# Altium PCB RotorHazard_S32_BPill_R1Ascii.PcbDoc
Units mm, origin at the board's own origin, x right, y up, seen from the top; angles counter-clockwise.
Board outline 100 x 100 mm, 2 copper layers (Top Layer, Bottom Layer), stack 1.671 mm thick; 43 components, 65 nets, 291 pads, 44 vias.
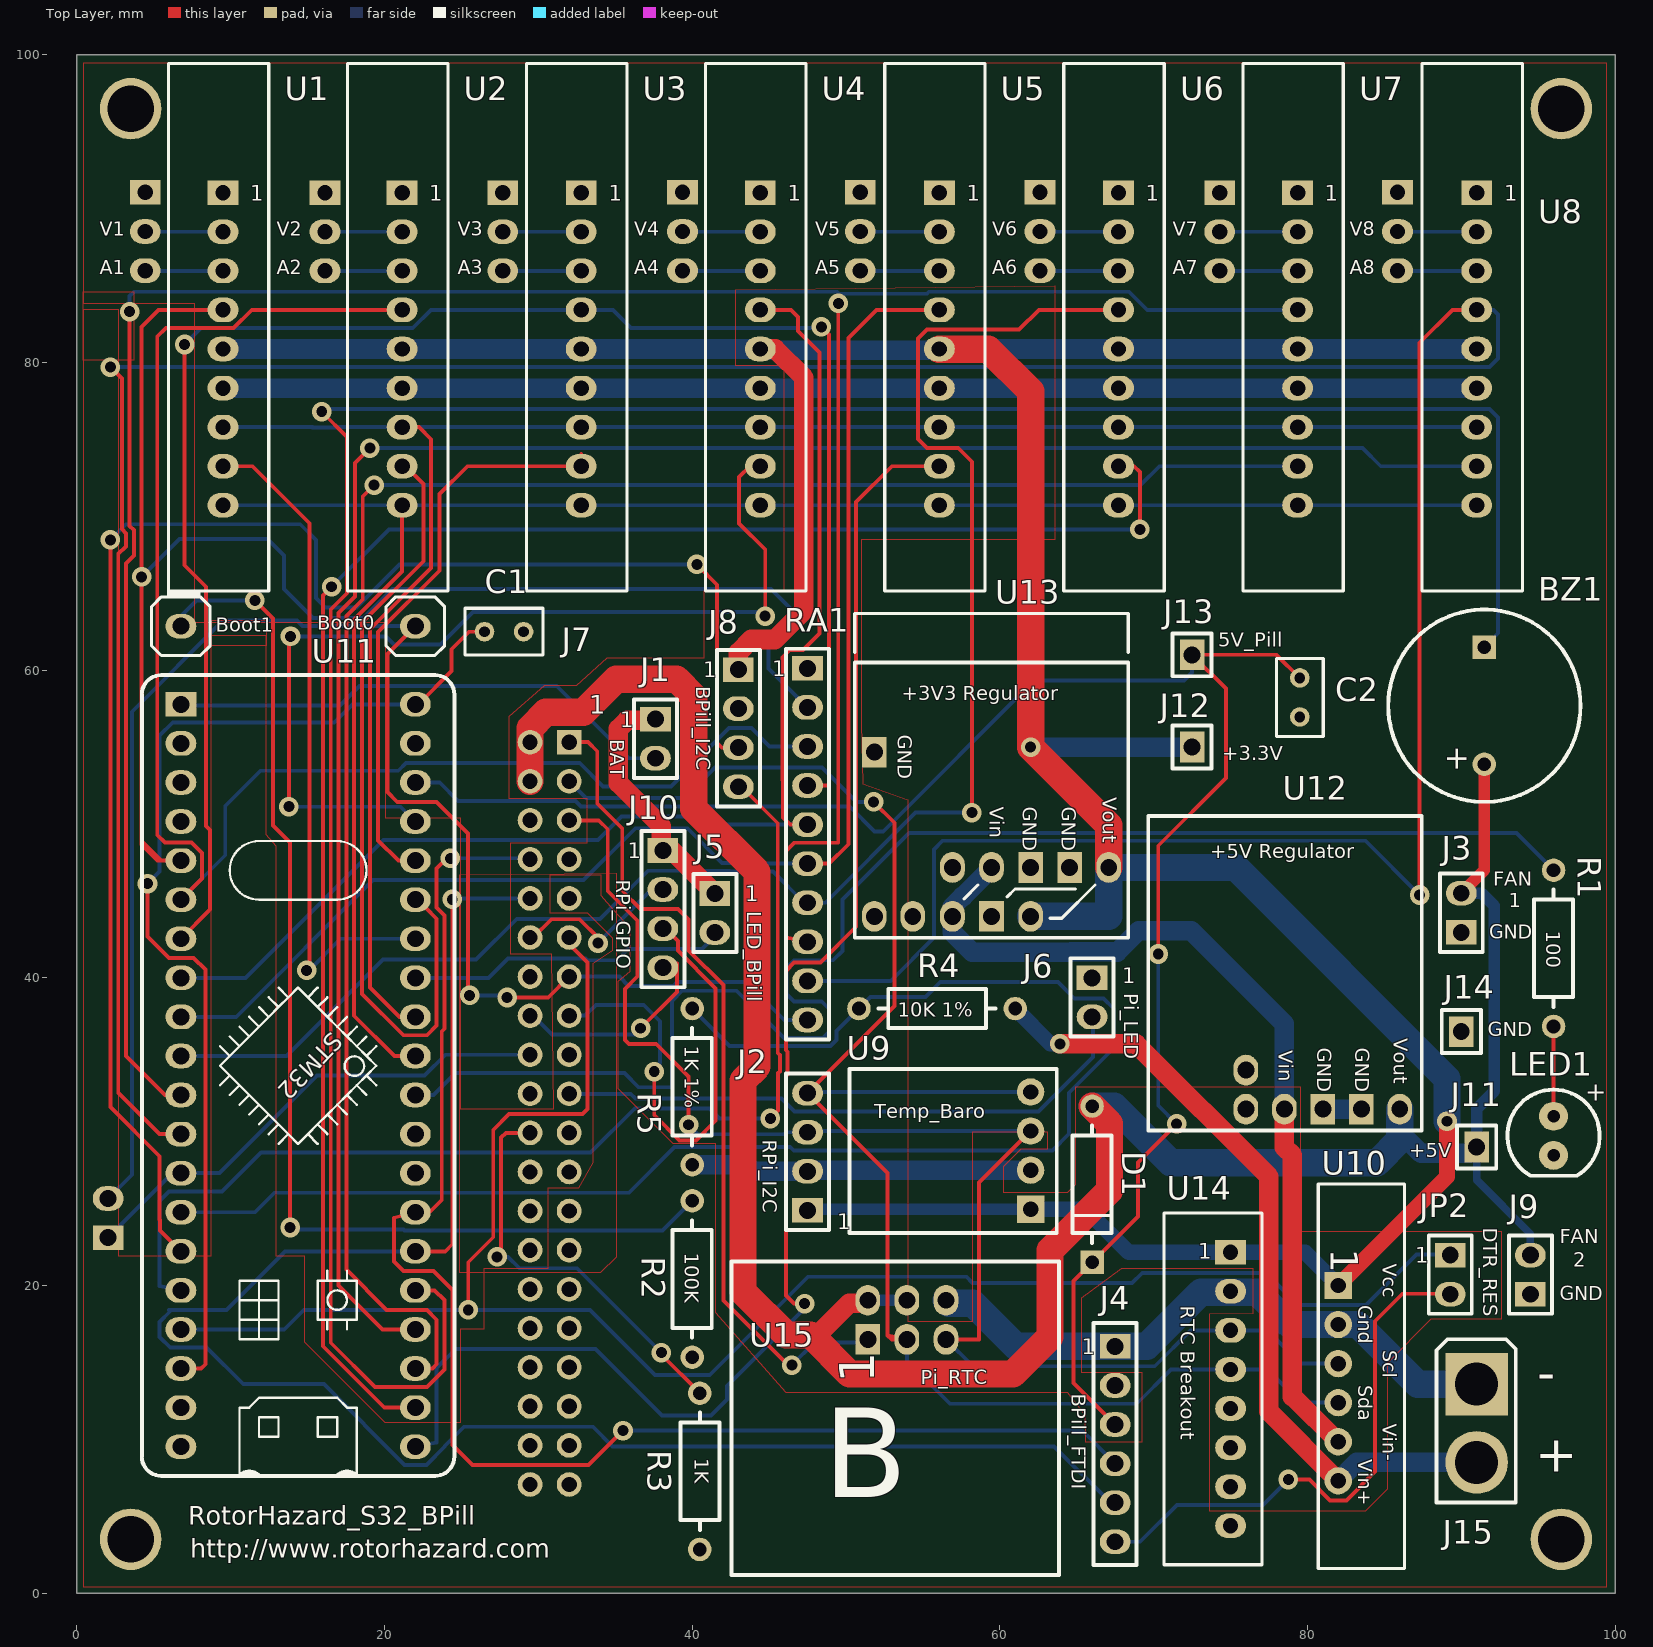
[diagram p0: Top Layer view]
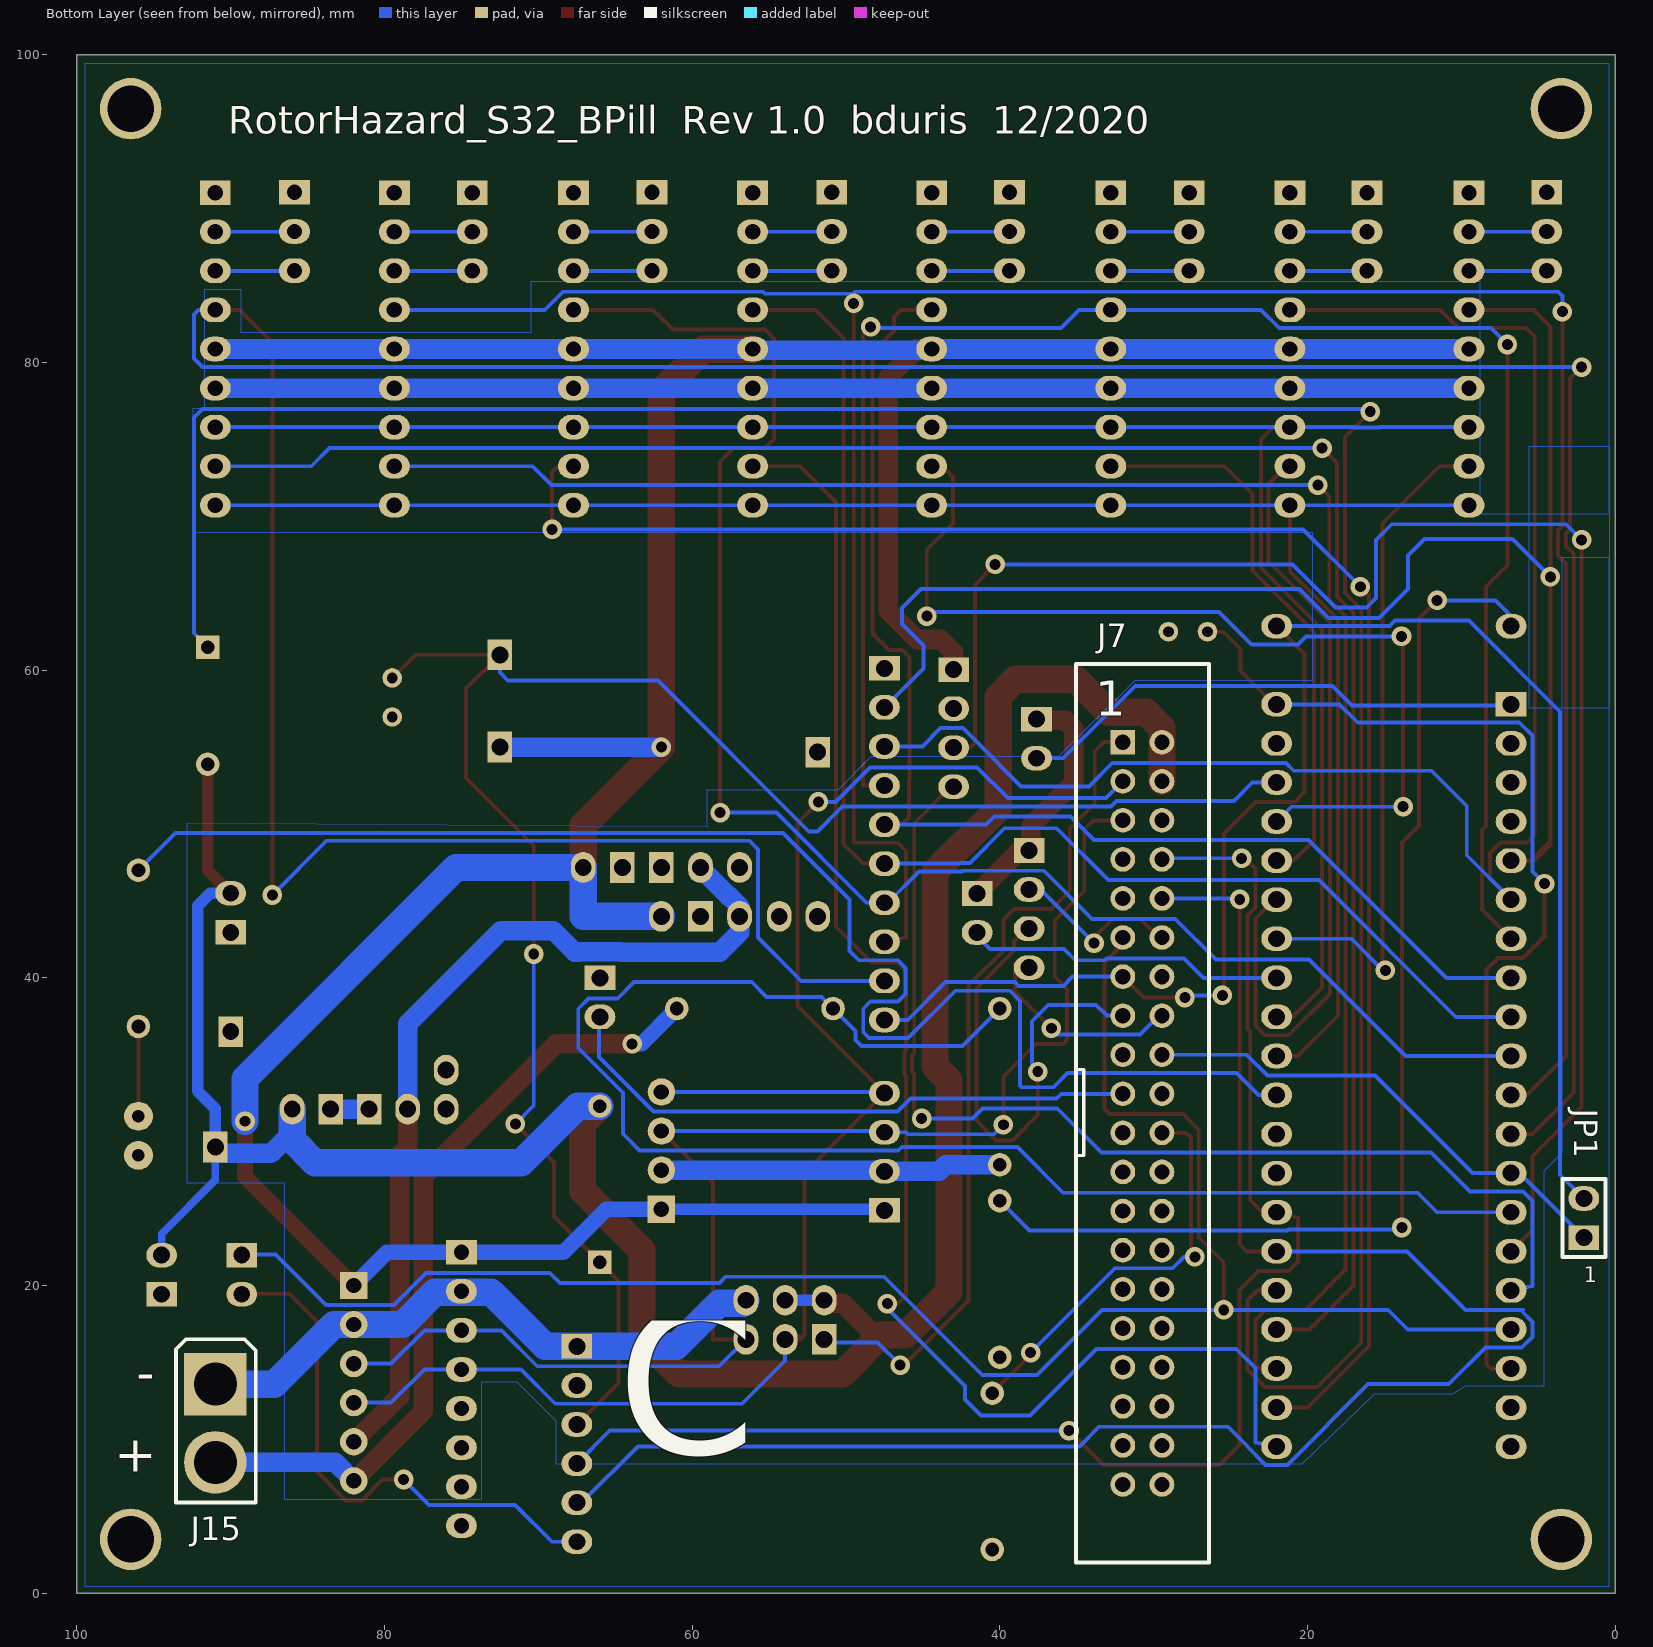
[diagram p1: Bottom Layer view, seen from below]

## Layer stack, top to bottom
Top Solder: solder mask 0.0102, Solder Resist, Dk 3.5
Top Layer: signal copper 0.0356
Dielectric 1: dielectric 1.6, FR-4, Dk 4.8
Bottom Layer: signal copper 0.0356
Bottom Solder: solder mask 0.0102, Solder Resist, Dk 3.5

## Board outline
0,0 100,0 100,100 0,100

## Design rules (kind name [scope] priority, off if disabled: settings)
AssemblyTestPointUsage [All] p0: scope1count=1 scope1_0_kind=Board scope1_0_value=Board scope2count=1 scope2_0_kind=Board scope2_0_value=Board commentlength=0
AssemblyTestpoint [All] p0: scope1count=1 scope1_0_kind=Board scope1_0_value=Board scope2count=1 scope2_0_kind=Board scope2_0_value=Board commentlength=0
Clearance [All] p0: scope1count=1 scope1_0_kind=Board scope1_0_value=Board scope2count=1 scope2_0_kind=Board scope2_0_value=Board commentlength=0 gap=0.254
Clearance [All] p1: gap=0.254
ComponentClearance [All] p0: scope1count=1 scope1_0_kind=Board scope1_0_value=Board scope2count=1 scope2_0_kind=Board scope2_0_value=Board commentlength=0 gap=0.254 collisioncheckmode=3
DiffPairsRouting [All] p0: scope1count=1 scope1_0_kind=Board scope1_0_value=Board scope2count=1 scope2_0_kind=Board scope2_0_value=Board commentlength=0
FabricationTestPointUsage [All] p0: scope1count=1 scope1_0_kind=Board scope1_0_value=Board scope2count=1 scope2_0_kind=Board scope2_0_value=Board commentlength=0 valid=0 allowmultiple=FALSE
FabricationTestpoint [All] p0: scope1count=1 scope1_0_kind=Board scope1_0_value=Board scope2count=1 scope2_0_kind=Board scope2_0_value=Board commentlength=0 side=3 testpointundercomponent=TRUE minsize=1.016 maxsize=2.54 preferedsize=1.524 minholesize=0 maxholesize=1.016 preferedholesize=0.813 testpointgrid=0.025
FanoutControl Fanout_Default [All] p0: scope1count=1 scope1_0_kind=Board scope1_0_value=Board scope2count=1 scope2_0_kind=Board scope2_0_value=Board commentlength=30 // Fanout_Default (Default Rule)
FanoutControl Fanout_Small [All] p0 off: scope1count=1 scope1_0_kind=Board scope1_0_value=Board scope2count=1 scope2_0_kind=Board scope2_0_value=Board commentlength=84 // Protel DXP Scope 1 Expression Was: (CompPinCount < 5)   Fanout_Small (Default Rule)
FanoutControl Fanout_SOIC [All] p0 off: scope1count=1 scope1_0_kind=Board scope1_0_value=Board scope2count=1 scope2_0_kind=Board scope2_0_value=Board commentlength=71 // Protel DXP Scope 1 Expression Was: IsSOIC   Fanout_SOIC (Default Rule)
FanoutControl Fanout_LCC [All] p0 off: scope1count=1 scope1_0_kind=Board scope1_0_value=Board scope2count=1 scope2_0_kind=Board scope2_0_value=Board commentlength=69 // Protel DXP Scope 1 Expression Was: IsLCC   Fanout_LCC (Default Rule)
FanoutControl Fanout_BGA [All] p0 off: scope1count=1 scope1_0_kind=Board scope1_0_value=Board scope2count=1 scope2_0_kind=Board scope2_0_value=Board commentlength=69 // Protel DXP Scope 1 Expression Was: IsBGA   Fanout_BGA (Default Rule)
Height [All] p0: scope1count=1 scope1_0_kind=Board scope1_0_value=Board scope2count=1 scope2_0_kind=Board scope2_0_value=Board commentlength=0
Height [All] p1: minheight=0 maxheight=38.1 prefheight=12.7
HoleSize [All] p0: scope1count=1 scope1_0_kind=Board scope1_0_value=Board scope2count=1 scope2_0_kind=Board scope2_0_value=Board commentlength=0 absolutevalues=TRUE maxlimit=6.35 minlimit=0.025 maxpercent=80.000 minpercent=20.000
HoleSize [All] p1: absolutevalues=TRUE maxlimit=6.35 minlimit=0.025 maxpercent=80.000 minpercent=20.000
HoleToHoleClearance [All] p0: scope1count=1 scope1_0_kind=Board scope1_0_value=Board scope2count=1 scope2_0_kind=Board scope2_0_value=Board commentlength=0
LayerPairs [All] p0: scope1count=1 scope1_0_kind=Board scope1_0_value=Board scope2count=1 scope2_0_kind=Board scope2_0_value=Board commentlength=0 enforce=TRUE
MinimumSolderMaskSliver [All] p0: scope1count=1 scope1_0_kind=Board scope1_0_value=Board scope2count=1 scope2_0_kind=Board scope2_0_value=Board commentlength=0
NetAntennae [All] p0: scope1count=1 scope1_0_kind=Board scope1_0_value=Board scope2count=1 scope2_0_kind=Board scope2_0_value=Board commentlength=0
PasteMaskExpansion [All] p0: scope1count=1 scope1_0_kind=Board scope1_0_value=Board scope2count=1 scope2_0_kind=Board scope2_0_value=Board commentlength=0 expansion=0
PlaneClearance [All] p0: scope1count=1 scope1_0_kind=Board scope1_0_value=Board scope2count=1 scope2_0_kind=Board scope2_0_value=Board commentlength=0 clearance=0.508
PlaneConnect [All] p0: scope1count=1 scope1_0_kind=Board scope1_0_value=Board scope2count=1 scope2_0_kind=Board scope2_0_value=Board commentlength=0 planeconnectstyle=Relief reliefexpansion=0.508 reliefentries=4 reliefconductorwidth=0.381 reliefairgap=0.254
PlaneConnect [All] p1: planeconnectstyle=Relief reliefexpansion=0.508 reliefentries=4 reliefconductorwidth=0.381 reliefairgap=0.254
PolygonConnect [All] p0: scope1count=1 scope1_0_kind=Board scope1_0_value=Board scope2count=1 scope2_0_kind=Board scope2_0_value=Board commentlength=0 connectstyle=Relief reliefconductorwidth=0.381 reliefentries=4 polygonreliefangle="90 Angle"
PolygonConnect [All] p1: connectstyle=Relief reliefconductorwidth=0.381 reliefentries=4 polygonreliefangle="90 Angle" airgapwidth=0.254
RoutingCorners [All] p0: scope1count=1 scope1_0_kind=Board scope1_0_value=Board scope2count=1 scope2_0_kind=Board scope2_0_value=Board commentlength=0 cornerstyle=45-Degree minsetback=2.54 maxsetback=2.54
RoutingLayers [All] p0: scope1count=1 scope1_0_kind=Board scope1_0_value=Board scope2count=1 scope2_0_kind=Board scope2_0_value=Board commentlength=0 top layer=Automatic bottom layer=Automatic
RoutingPriority [All] p0: scope1count=1 scope1_0_kind=Board scope1_0_value=Board scope2count=1 scope2_0_kind=Board scope2_0_value=Board commentlength=0
RoutingTopology [All] p0: scope1count=1 scope1_0_kind=Board scope1_0_value=Board scope2count=1 scope2_0_kind=Board scope2_0_value=Board commentlength=0 topology=Shortest
RoutingVias [All] p0: scope1count=1 scope1_0_kind=Board scope1_0_value=Board scope2count=1 scope2_0_kind=Board scope2_0_value=Board commentlength=0 holewidth=0.711 width=1.27 viastyle="Through Hole" minholewidth=0.711 minwidth=1.27 maxholewidth=0.711 maxwidth=1.27
RoutingVias [All] p1: holewidth=0.711 width=1.27 viastyle="Through Hole" minholewidth=0.711 minwidth=1.27 maxholewidth=0.711 maxwidth=1.27
ShortCircuit [All] p0: scope1count=1 scope1_0_kind=Board scope1_0_value=Board scope2count=1 scope2_0_kind=Board scope2_0_value=Board commentlength=0 allowed=FALSE
SilkToBoardRegionClearance [All] p0: scope1count=1 scope1_0_kind=Board scope1_0_value=Board scope2count=1 scope2_0_kind=Board scope2_0_value=Board commentlength=0
SilkToSilkClearance [All] p0: scope1count=1 scope1_0_kind=Board scope1_0_value=Board scope2count=1 scope2_0_kind=Board scope2_0_value=Board commentlength=0
SilkToSilkClearance [All] p1: silktosilkclearance=0.152
SilkToSolderMaskClearance [All] p0 off: scope1count=1 scope1_0_kind=Board scope1_0_value=Board scope2count=1 scope2_0_kind=Board scope2_0_value=Board commentlength=44 // Protel DXP Scope 1 Expression Was: IsPad
SilkToSolderMaskClearance [IsPad] p1: minsilkscreentomaskgap=0.152 clearancetoexposedcopper=TRUE
SolderMaskExpansion [All] p0: scope1count=1 scope1_0_kind=Board scope1_0_value=Board scope2count=1 scope2_0_kind=Board scope2_0_value=Board commentlength=0 expansion=0.102
SolderMaskExpansion [All] p1: expansion=0.102
UnRoutedNet [All] p0: scope1count=1 scope1_0_kind=Board scope1_0_value=Board scope2count=1 scope2_0_kind=Board scope2_0_value=Board commentlength=0
UnpouredPolygon [All] p0: scope1count=1 scope1_0_kind=Board scope1_0_value=Board scope2count=1 scope2_0_kind=Board scope2_0_value=Board commentlength=0
Width Width_5 [All] p0: scope1count=1 scope1_0_kind=Net scope1_0_value=+5V scope2count=1 scope2_0_kind=Board scope2_0_value=Board commentlength=0 maxlimit=2.54 minlimit=0.508 preferedwidth=0.762
Width Width_1 [All] p0: scope1count=1 scope1_0_kind=Board scope1_0_value=Board scope2count=1 scope2_0_kind=Board scope2_0_value=Board commentlength=0 maxlimit=0.254 minlimit=0.254 preferedwidth=0.254
Width Width_3V3 [All] p0: scope1count=1 scope1_0_kind=Net scope1_0_value=+3V3 scope2count=1 scope2_0_kind=Board scope2_0_value=Board commentlength=0 maxlimit=2.54 minlimit=0.762 preferedwidth=1.016
Width Width_GND [All] p0: scope1count=1 scope1_0_kind=Net scope1_0_value=GND scope2count=1 scope2_0_kind=Board scope2_0_value=Board commentlength=0 maxlimit=2.54 minlimit=0.762 preferedwidth=1.27
Width Width_VPWR_IN+ [All] p0: scope1count=1 scope1_0_kind=Net scope1_0_value=VPWR_IN+ scope2count=1 scope2_0_kind=Board scope2_0_value=Board commentlength=0 maxlimit=1.27 minlimit=0.762 preferedwidth=1.016
Width Width_VPWR_IN- [All] p0: scope1count=1 scope1_0_kind=Net scope1_0_value=VPWR_IN- scope2count=1 scope2_0_kind=Board scope2_0_value=Board commentlength=0 maxlimit=1.27 minlimit=0.762 preferedwidth=1.016
Width Width_GND [InNet('GND')] p1: maxlimit=2.54 minlimit=0.762 preferedwidth=1.27
Width Width_3V3 [InNet('+3V3')] p2: maxlimit=2.54 minlimit=0.762 preferedwidth=1.016
Width Width_5 [InNet('+5V')] p3: maxlimit=2.54 minlimit=0.508 preferedwidth=0.762
Width Width_VPWR_IN+ [InNet('VPWR_IN+')] p4: maxlimit=1.27 minlimit=0.762 preferedwidth=1.016
Width Width_VPWR_IN- [InNet('VPWR_IN-')] p5: maxlimit=1.27 minlimit=0.762 preferedwidth=1.016
Width Width_1 [All] p6: maxlimit=0.254 minlimit=0.254 preferedwidth=0.254
25 further rules are at their usual default settings.

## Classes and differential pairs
net class RSSI_[1..8]: RSSI_1 RSSI_2 RSSI_3 RSSI_4 RSSI_5 RSSI_6 RSSI_7 RSSI_8
net class RX_SEL_[1..8]: RX_SEL_1 RX_SEL_2 RX_SEL_3 RX_SEL_4 RX_SEL_5 RX_SEL_6 RX_SEL_7 RX_SEL_8

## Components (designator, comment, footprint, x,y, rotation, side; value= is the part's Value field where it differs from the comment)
BZ1 "TMB12A05" BZ_12mm 91.5,61.5 r90 top
C1 "0.1uF 50V X7R" "Cap Radial 100mil" 29.04,62.5 r180 top
C2 "0.1uF 50V X7R" "Cap Radial 100mil" 79.5,56.96 r90 top
D1 "MBR100RLG" "Axial 0.4 Diode" 66,31.66 r270 top
J1 "HDR 1X2" "HDR 1x2_2.54mm" 37.611,56.813 r0 top
J2 "HDR 1X4" "HDR 1x4_2.54mm" 47.5,24.88 r180 top
J3 "HDR 1X2" "HDR 1x2_2.54mm" 90,42.96 r180 top
J4 "6 PIN SIL VERT SOCKET" "6-PIN SIL VERT SOCKET" 67.5,16.04 r0 top
J5 "HDR 1X2" "HDR 1x2_2.54mm" 41.472,45.485 r0 top
J6 "HDR 1X2" "HDR 1x2_2.54mm" 66,40 r0 top
J7 "Header_2X20_Vert_Thru" Header_2X20_Vert_Thru 30.73,31.19 r180 bottom
J8 "HDR 1X4" "HDR 1x4_2.54mm" 43,60.04 r0 top
J9 "HDR 1X2" "HDR 1x2_2.54mm" 94.488,19.431 r180 top
J10 "HDR 1X4" "HDR 1x4_2.54mm" 38.094,48.279 r0 top
J11 "HDR 1X1" "HDR 1x1_2.54mm" 91,29 r90 top
J12 "HDR 1X1" "HDR 1x1_2.54mm" 72.5,55 r90 top
J13 "HDR 1X1" "HDR 1x1_2.54mm" 72.5,61 r90 top
J14 "HDR 1X1" "HDR 1x1_2.54mm" 90,36.5 r90 top
J15 "XT30-M" XT30_M 91,13.58 r0 bottom
JP1 "HDR 1X2" "HDR 1x2_2.54mm" 2.032,23.114 r0 bottom
JP2 "HDR 1X2" "HDR 1x2_2.54mm" 89.281,21.971 r0 top
LED1 "LED_5mm" LED_5mm 96,31 r270 top
R1 "100 1/4W 5%" "Axial 0.4 100 CF" 96,36.84 r90 top
R2 "100K 1/4W 5%" "Axial 0.4 100K CF" 40,15.34 r90 top
R3 "1K 1/4W 5%" "Axial 0.4 1K CF" 40.5,2.84 r90 top
R4 "10K 1/4W 1%" "Axial 0.4 10K MF" 50.84,38 r0 top
R5 "1K 1/4W 1%" "Axial 0.4 1K MF" 40,27.84 r90 top
RA1 "100K 10Pin SIP" RES_SIP_10P 47.5,60.12 r0 top
U1 "RX5808_PCB" RH_S32_Node_PCB 9.5,91.04 r0 top
U2 "RX5808_PCB" RH_S32_Node_PCB 21.143,91.04 r0 top
U3 "RX5808_PCB" RH_S32_Node_PCB 32.786,91.04 r0 top
U4 "RX5808_PCB" RH_S32_Node_PCB 44.429,91.04 r0 top
U5 "RX5808_PCB" RH_S32_Node_PCB 56.071,91.04 r0 top
U6 "RX5808_PCB" RH_S32_Node_PCB 67.714,91.04 r0 top
U7 "RX5808_PCB" RH_S32_Node_PCB 79.357,91.04 r0 top
U8 "RX5808_PCB" RH_S32_Node_PCB 91,91.04 r0 top
U9 "BME280_BRD" BME280_PCB 62,24.96 r90 top
U10 "INA219_BRD" INA219_PCB_RA 82,20 r270 top
U11 "STM32F103XX BPill" DIP40_Plus2 14.38,36.19 r0 top
U12 "D36V28F5" D36V28FX 76,31.46 r0 top
U13 "D24V22F3" D24V22FX 51.84,44 r0 top
U14 "DS3231_BBRD" DS3231_Breakout 75,22.16 r0 top
U15 "DS3231_Pi_RTC" Pi_RTC 75.55,17.77 r90 top

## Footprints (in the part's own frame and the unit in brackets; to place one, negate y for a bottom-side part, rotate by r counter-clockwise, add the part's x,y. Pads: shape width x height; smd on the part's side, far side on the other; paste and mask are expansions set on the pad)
"6-PIN SIL VERT SOCKET" [mm]
  rect 2x1.6 hole 1.1: 1(0,0)
  oval 2x1.6 hole 1.1: 2(0,-2.54) 3(0,-5.08) 4(0,-7.62) 5(0,-10.16) 6(0,-12.7)
  silkscreen extent -1.4,-14.22 1.4,1.52
"Axial 0.4 1K CF" [mil]
  round 60 hole 35: 1(0,0) 2(400,0)
  silkscreen extent 50,-50 350,50
"Axial 0.4 1K MF" [mil]
  round 60 hole 35: 1(0,0) 2(400,0)
  silkscreen extent 50,-50 350,50
"Axial 0.4 10K MF" [mil]
  round 60 hole 35: 1(0,0) 2(400,0)
  silkscreen extent 50,-50 350,50
"Axial 0.4 100 CF" [mil]
  round 60 hole 35: 1(0,0) 2(400,0)
  silkscreen extent 50,-50 350,50
"Axial 0.4 100K CF" [mil]
  round 60 hole 35: 1(0,0) 2(400,0)
  silkscreen extent 50,-50 350,50
"Axial 0.4 Diode" [mil]
  round 60 hole 35: A(0,0)
  rect 60x60 hole 35: K(400,0)
  silkscreen extent 50,-50 350,50
BME280_PCB [mil] "BME280 Temp Humidity and Pressure Breakout Board"
  rect 70x70 hole 39.37: 1(0,0)
  round 70 hole 39.37: 2(100,0) 3(200,0) 4(300,0)
  silkscreen extent -61,-67 359,463
BZ_12mm [mil]
  rect 60x60 hole 35: 1(0,0)
  round 60 hole 35: 2(-300,0)
  silkscreen extent -396,-246 96,246
"Cap Radial 100mil" [mil]
  round 50 hole 28: 1(0,0) 2(100,0)
  silkscreen extent -50,-60 150,60
D24V22FX [mm] "Pololu D24V22FX Series pad layout and body"
  oval 1.6x2 hole 1.1: 1(0,0) 2(2.5,0) 3(5.08,0) 5(10.16,0)
  rect 1.6x2 hole 1.1: 4(7.62,0) 6(0,10.668)
  silkscreen extent -1.27,-1.4 16.51,16.51
D36V28FX [mm] "Pololu D36V28FX Series DC/DC Converter"
  oval 1.6x2 hole 1.1: 1(0,0) 2(2.5,0) 5(10,0) 6(0,2.54)
  rect 1.6x2 hole 1.1: 3(5,0) 4(7.5,0)
  silkscreen extent -6.35,-1.4 11.43,19.05
DIP40_Plus2 [mm]
  rect 2x1.6 hole 1.1: 1(-7.62,21.59)
  oval 2x1.6 hole 1.1: 2(-7.62,19.05) 3(-7.62,16.51) 4(-7.62,13.97) 5(-7.62,11.43) 6(-7.62,8.89) 7(-7.62,6.35) 8(-7.62,3.81) 9(-7.62,1.27) 10(-7.62,-1.27) 11(-7.62,-3.81) 12(-7.62,-6.35) 13(-7.62,-8.89) 14(-7.62,-11.43) 15(-7.62,-13.97) 16(-7.62,-16.51) 17(-7.62,-19.05) 18(-7.62,-21.59) 19(-7.62,-24.13) 20(-7.62,-26.67) 21(7.62,-26.67) 22(7.62,-24.13) 23(7.62,-21.59) 24(7.62,-19.05) 25(7.62,-16.51) 26(7.62,-13.97) 27(7.62,-11.43) 28(7.62,-8.89) 29(7.62,-6.35) 30(7.62,-3.81) 31(7.62,-1.27) 32(7.62,1.27) 33(7.62,3.81) 34(7.62,6.35) 35(7.62,8.89) 36(7.62,11.43) 37(7.62,13.97) 38(7.62,16.51) 39(7.62,19.05) 40(7.62,21.59) 41(7.62,26.67) 42(-7.62,26.67)
  silkscreen extent -10.16,-28.57 10.16,28.57
DS3231_Breakout [mm] "Adafruit DS3231 RTC Breakout Board"
  rect 2x1.6 hole 1: 1(0,0)
  oval 2x1.6 hole 1: 2(0,-2.54) 3(0,-5.08) 4(0,-7.62) 5(0,-10.16) 6(0,-12.7) 7(0,-15.24) 8(0,-17.78)
  silkscreen extent -4.32,-20.32 2.03,2.54
"HDR 1x1_2.54mm" [mm]
  rect 2x1.6 hole 1.1: 1(0,0)
  silkscreen extent -1.4,-1.27 1.4,1.27
"HDR 1x2_2.54mm" [mm]
  rect 2x1.6 hole 1.1: 1(0,0)
  oval 2x1.6 hole 1.1: 2(0,-2.54)
  silkscreen extent -1.4,-3.81 1.4,1.27
"HDR 1x4_2.54mm" [mm]
  rect 2x1.6 hole 1.1: 1(0,0)
  oval 2x1.6 hole 1.1: 2(0,-2.54) 3(0,-5.08) 4(0,-7.62)
  silkscreen extent -1.4,-8.89 1.4,1.27
Header_2X20_Vert_Thru [mm]
  rect 1.6x1.6 hole 1: 1(-1.27,24.13)
  round 1.6 hole 1: 2(1.27,24.13) 3(-1.27,21.59) 4(1.27,21.59) 5(-1.27,19.05) 6(1.27,19.05) 7(-1.27,16.51) 8(1.27,16.51) 9(-1.27,13.97) 10(1.27,13.97) 11(-1.27,11.43) 12(1.27,11.43) 13(-1.27,8.89) 14(1.27,8.89) 15(-1.27,6.35) 16(1.27,6.35) 17(-1.27,3.81) 18(1.27,3.81) 19(-1.27,1.27) 20(1.27,1.27) 21(-1.27,-1.27) 22(1.27,-1.27) 23(-1.27,-3.81) 24(1.27,-3.81) 25(-1.27,-6.35) 26(1.27,-6.35) 27(-1.27,-8.89) 28(1.27,-8.89) 29(-1.27,-11.43) 30(1.27,-11.43) 31(-1.27,-13.97) 32(1.27,-13.97) 33(-1.27,-16.51) 34(1.27,-16.51) 35(-1.27,-19.05) 36(1.27,-19.05) 37(-1.27,-21.59) 38(1.27,-21.59) 39(-1.27,-24.13) 40(1.27,-24.13)
  silkscreen extent -4.32,-29.21 4.32,29.21
INA219_PCB_RA [mil] "Current and Voltage Sensor PCB with right-angle pins"
  rect 70x70 hole 39.37: 1(0,0)
  round 70 hole 39.37: 2(100,0) 3(200,0) 4(300,0) 5(400,0) 6(500,0)
  silkscreen extent -260,-51 724,169
LED_5mm [mil]
  round 74 hole 32: A(0,0) K(100,0)
  silkscreen extent -68,-118 152,118
Pi_RTC [mm] "Pins 1-6 of Pi header broken out for RTC"
  rect 2x1.6 hole 1.1: 1(-1.27,24.13)
  oval 2x1.6 hole 1.1: 2(1.27,24.13) 3(-1.27,21.59) 4(1.27,21.59) 5(-1.27,19.05) 6(1.27,19.05)
  silkscreen extent -16.6,11.7 3.8,33
RES_SIP_10P [mm] "Resistor Array 10-pin SIP"
  rect 2x1.6 hole 1.1: 1(0,0)
  oval 2x1.6 hole 1.1: 2(0,-2.54) 3(0,-5.08) 4(0,-7.62) 5(0,-10.16) 6(0,-12.7) 7(0,-15.24) 8(0,-17.78) 9(0,-20.32) 10(0,-22.86)
  silkscreen extent -1.4,-24.13 1.4,1.27
RH_S32_Node_PCB [mm] "RX5808 Module on PCB with RA Pins"
  rect 2x1.6 hole 1: 1(0,0)
  oval 2x1.6 hole 1: 2(0,-2.54) 3(0,-5.08) 4(0,-7.62) 5(0,-10.16) 6(0,-12.7) 7(0,-15.24) 8(0,-17.78) 9(0,-20.32)
  silkscreen extent -3.56,-25.88 2.97,8.41
XT30_M [mil] "XT30 connector male pins"
  rect 160x160 hole 110: 1(0,0)
  round 160 hole 110: 2(0,200)
  silkscreen extent -103,-115 100,303

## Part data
BZ1: library part Buzzer_12mm, "TMB12A05 12mmX9.5mm Buzzer"
C1 C2: library part C320C104K5R5TA7301, "Multilayer Ceramic Capacitors MLCC - Leaded 50V 0.1uF 10% X7R"
D1: library part MBR1100RLG, "Schottky Diodes & Rectifiers 1A 100V"
J1 J3 J5 J6 J9 JP1 JP2: library part 961102-6804-AR, "Headers & Wire Housings 2P STRT 1 ROW GOLD 6.8MM MATING PIN"
J2 J8 J10: library part 961104-6804-AR, "Headers & Wire Housings 4P STRT 1 ROW GOLD 6.8MM MATING PIN"
J4: library part M20-7820646, "Headers & Wire Housings 6 PIN SIL VERTICAL SOCKET TIN"
J7: library part Header_To_Pi_Cable
J11 J12 J13 J14: library part "HEADER 1X1", "Single pin header"
J15: "XT30 connector male pins"
LED1: "5mm standard leaded red LED"
R1: library part CFR-25JR-52-100R, "Carbon Film Resistors - Through Hole 100ohm 1/4W 5%"
R2: library part CFR-25JR-52-100K, "Carbon Film Resistors - Through Hole 100K ohm 1/4W 5%"
R3: library part CFR-25JT-52-1K, "Carbon Film Resistors - Through Hole 1/4W 1K Ohm 5%"
R4: library part MFR-25FRF52-10K, "Metal Film Resistors - Through Hole 10K ohm 1/4W 1%"
R5: library part MFR-25FRF52-1K, "Metal Film Resistors - Through Hole 1K ohm 1/4W 1%"
RA1: library part 4610X-101-104LF, "Resistor Networks & Arrays 10pins 100Kohms Bussed"
U1 U2 U3 U4 U5 U6 U7 U8: library part RH_S32_Node, "RX5808 module on PCB with right-angle header pins"
U9: library part BME280, "BME280 Temperature, Humidity and Pressure Sensor"
U10: "INA219 Current Sensor/Voltage Monitor"
U11: library part STM32F103XX_BPill, "STMF103XX BPill"
U12: "Pololu D36V28F5 DC/DC Converter"
U13: "Pololu D24V22F3 DC/DC Converter"
U14: library part DS3231_Breakout, "ADAFruit DS3231 Breakout Board"
U15: "ADAFruit DS3231 PiRTC"

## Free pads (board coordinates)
  round 4 hole 3: 0(96.5,96.5) 1(96.5,3.5) 2(3.5,3.5) 3(3.5,96.5)
  rect 2x1.6 hole 1: 1(4.445,91.059) 1(16.129,91.04) 1(27.686,91.04) 1(50.927,91.059) 1(62.611,91.059) 1(74.295,91.04) 1(85.852,91.059) 7(39.37,91.059)
  oval 1.6x2 hole 1.1: 1(56.92,47.175) 2(59.46,47.175) 5(67.08,47.175)
  oval 2x1.6 hole 1: 2(4.445,88.519) 2(16.129,88.5) 2(27.686,88.5) 2(39.37,88.519) 2(50.927,88.519) 2(62.611,88.519) 2(74.295,88.5) 2(85.852,88.519) 3(4.445,85.979) 3(16.129,85.96) 3(27.686,85.96) 3(39.37,85.979) 3(50.927,85.979) 3(62.611,85.979) 3(74.295,85.96) 3(85.852,85.979)
  rect 1.6x2 hole 1.1: 3(62,47.175) 4(64.54,47.175)

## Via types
v1: diameter 1.27, hole 0.711, Top Layer to Bottom Layer, 44 vias

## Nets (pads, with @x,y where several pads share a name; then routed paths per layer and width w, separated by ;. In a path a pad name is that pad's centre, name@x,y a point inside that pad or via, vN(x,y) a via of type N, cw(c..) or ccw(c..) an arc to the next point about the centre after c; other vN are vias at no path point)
3V3_PILL: C1.2 U11.18 U11.40 | length 70.1
  Top Layer w0.254: v1(4.591,46.12) 4.591,42.691 5.988,41.294 7.588,41.294 8.35,40.532 8.35,14.879 8.071,14.6 U11.18 ; U11.40 22.193,57.78 24.352,59.939 24.352,61.36 25.492,62.5 C1.2
  Bottom Layer w0.254: v1(4.591,46.12) 5.378,46.907 5.378,55.747 6.231,56.599 16.728,56.599 17.909,57.78 U11.40
5V_PILL: C2.2 D1.K J4.3 J13.1 U11.38 | length 122
  Top Layer w0.254: J4.3 64.789,13.671 64.789,20.289 D1.K 68.98,24.48 68.98,27.984 v1(71.495,30.499) ; v1(70.301,41.548) 70.301,48.584 74.695,52.978 74.695,58.805 J13.1 78,61 C2.2
  Bottom Layer w0.254: U11.38 23.589,52.7 24.784,51.505 32.405,51.505 32.769,51.141 50.243,51.141 51.86,49.524 52.419,49.524 62.224,59.328 71.992,59.328 72.5,59.836 J13.1 ; v1(70.301,41.548) 70.301,31.693 v1(71.495,30.499)
+3V3: J2.1 J8.1 J12.1 pad.5 U1.5 U2.5 U3.5 U4.5 U5.5 U6.5 U7.5 U8.5 U9.1 U10.1 U13.5 U14.1 | length 246.4
  Top Layer w1.016: J8.1 J8.1@43.021,60.04 ; U10.1 89.071,27.071 v1(89.071,30.677)
  Top Layer w1.27: J8.1 43,61.161 43.834,61.995 45.38,61.995 47.263,63.878 47.263,79.013 45.396,80.88 U4.5
  Top Layer w1.778: U5.5@56.071,80.867 59.257,80.867 62,78.124 62,55.005 v1(62.005,55) 67.08,49.925 pad.5
  Bottom Layer w0.762: J2.1 47.58,24.96 U9.1
  Bottom Layer w1.016: U9.1 65.57,24.96 68.37,22.16 U14.1 79.84,22.16 U10.1 ; U13.5 U13.5@62,44.012
  Bottom Layer w1.27: U1.5 U2.5 U3.5 U4.5 44.518,80.791 55.982,80.791 U5.5 U6.5 U7.5 U8.5 ; v1(62.005,55) J12.1
  Bottom Layer w1.778: U13.5 67.08,44 pad.5 75.335,47.175 89.071,33.439 v1(89.071,30.677)
+5V: BZ1.2 D1.A J3.2 J7.2 J7.4 J9.2 J11.1 U12.5 U15.2 U15.4 | length 171.7
  Top Layer w0.762: U15.2@51.42,18.84 U15.2 ; J3.2 91.5,47 BZ1.2
  Top Layer w1.27: 47.695,16.783 48.152,16.783 50.209,18.84 U15.2@51.42,18.84
  Top Layer w1.778: J7.4 29.46,56.232 30.491,57.263 32.93,57.263 35.071,59.404 38.983,59.404 40.1,58.287 40.1,50.997 44.215,46.882 44.215,34.233 43.301,33.318 43.301,19.602 46.12,16.783 47.695,16.783 50.235,14.243 60.852,14.243 63.265,16.656 63.265,22.295 67.126,26.156 67.126,30.534 D1.A
  Bottom Layer w0.508: J11.1@90.594,28.594 J11.1 91,26.856 94.488,23.368 J9.2
  Bottom Layer w0.762: J7.2@29.458,55.32 J7.2 ; U15.2 U15.4 ; J3.2 91.332,45.5 92.145,44.687 92.145,32.636 91,31.491 J11.1
  Bottom Layer w1.27: U12.5 86,29.989 87.395,28.594 J11.1@90.594,28.594
  Bottom Layer w1.778: D1.A 67.438,31.66 71.114,27.984 84.525,27.984 86,29.46 U12.5
AUD1: pad.3@4.445,85.979 U1.3 | length 5.1
  Bottom Layer w0.254: pad.3@4.445,85.979 4.464,85.96 U1.3
AUD2: pad.3@16.129,85.96 U2.3 | length 5
  Bottom Layer w0.254: pad.3@16.129,85.96 U2.3
AUD3: pad.3@27.686,85.96 U3.3 | length 5.1
  Bottom Layer w0.254: pad.3@27.686,85.96 U3.3
AUD4: pad.3@39.37,85.979 U4.3 | length 5.1
  Bottom Layer w0.254: pad.3@39.37,85.979 39.389,85.96 U4.3
AUD5: pad.3@50.927,85.979 U5.3 | length 5.2
  Bottom Layer w0.254: pad.3@50.927,85.979 50.946,85.96 U5.3
AUD6: pad.3@62.611,85.979 U6.3 | length 5.1
  Bottom Layer w0.254: pad.3@62.63,85.96 U6.3
AUD7: pad.3@74.295,85.96 U7.3 | length 5.1
  Bottom Layer w0.254: pad.3@74.295,85.96 U7.3
AUD8: pad.3@85.852,85.979 U8.3 | length 5.1
  Bottom Layer w0.254: pad.3@85.871,85.96 U8.3
BOOT0: J7.13 JP1.2 RA1.10 U11.41 | length 106.1
  Top Layer w0.254: U11.41 20.193,61.053 20.193,52.07 20.828,51.435 23.368,51.435 25.419,49.384 25.419,38.862 v1(25.527,38.862) ; v1(27.975,38.721) 30.613,38.721 30.627,38.735 30.641,38.721 J7.13
  Bottom Layer w0.254: JP1.2 3.575,27.197 3.575,57.296 9.496,63.217 14.306,63.217 14.662,62.86 U11.41 ; v1(25.527,38.862) 27.94,38.862 27.975,38.827 v1(27.975,38.721) ; J7.13@31.794,40.08 35.269,40.08 35.871,39.478 38.783,39.478 39.024,39.719 43.529,39.719 45.988,37.26 RA1.10
BOOT1: R2.2 U11.42 | length 74.9
  Top Layer w0.254: v1(11.576,64.535) 12.744,63.367 12.744,49.905 13.862,48.787 v1(13.862,23.768)
  Bottom Layer w0.254: U11.42 6.76,63.529 7.766,64.535 v1(11.576,64.535) ; v1(13.862,23.768) 13.735,23.641 21.249,23.641 21.311,23.579 38.079,23.579 R2.2
BPILL_PB0: J7.18 JP1.1 U11.13 | length 32.7
  Bottom Layer w0.254: JP1.1 6.218,27.3 U11.13 ; U11.13@6.76,26.792 6.97,26.792 7.268,27.09 7.268,27.3 9.266,27.3 15.621,33.655 22.605,33.655 23.95,35 J7.18
BPILL_RESET: J7.11 JP2.1 U11.17 | length 121
  Top Layer w0.254: v1(25.444,18.409) 25.444,21.507 27.07,23.133 27.07,30.118 28.086,31.134 32.861,31.134 33.191,31.464 33.191,40.989 31.857,42.324 31.857,42.62 J7.11
  Bottom Layer w0.254: U11.17 13.482,17.14 14.751,18.409 15.385,18.409 v1(25.444,18.409) 33.369,18.409 37.586,14.192 41.142,14.192 47.517,20.568 57.829,20.568 58.236,20.161 68.599,20.161 69.259,20.822 77.3,20.822 79.392,18.73 83.814,18.73 87.084,22 JP2.1@89.252,22
BPILL_SCL: J8.3 U11.15 | length 106
  Top Layer w0.254: v1(2.178,68.472) 2.178,31.604 5.379,28.403 5.379,24.271 5.401,24.249 5.401,23.579 U11.15 ; v1(40.303,66.872) 41.619,65.556 41.619,55.264 41.923,54.96 J8.3
  Bottom Layer w0.254: v1(2.178,68.472) 3.194,69.488 14.522,69.488 15.538,68.472 15.538,64.687 16.148,64.078 18.18,64.078 20.974,66.872 v1(40.303,66.872)
BPILL_SDA: J8.4 U11.16 | length 72.5
  Top Layer w0.254: J8.4 43.196,52.42 45.564,50.051 45.564,35.105 45.698,34.971 45.698,33.919 45.587,33.808 45.587,31.363 v1(45.079,30.855)
  Bottom Layer w0.254: U11.16 5.378,19.958 5.378,25.495 5.988,26.105 9.442,26.105 11.982,28.645 33.395,28.645 36.265,31.515 41.116,31.515 41.777,30.855 v1(45.079,30.855)
BZ_DRV: BZ1.1 U11.25 | length 169.4
  Top Layer w0.254: v1(15.919,76.803) 17.57,75.152 17.57,65.003 16.504,63.936 16.504,16.275 19.374,13.405 22.752,13.405 23.895,14.548 23.895,19.045 23.26,19.68 U11.25
  Bottom Layer w0.254: v1(15.919,76.803) 16.097,76.981 91.84,76.981 92.399,76.422 92.399,62.399 BZ1.1
CTS: J4.2
DTR: J4.6 JP2.2 | length 35.3
  Top Layer w0.254: v1(78.759,7.385) 80.119,7.385 81.474,6.03 82.526,6.03 84.389,7.893 84.389,17.672 86.177,19.46 JP2.2@89.252,19.46
  Bottom Layer w0.254: J4.6 69.126,3.34 71.52,5.734 77.108,5.734 v1(78.759,7.385)
GND: C1.1 C2.1 J1.1 J2.2 J3.1 J4.1 J5.1 J6.1 J7.6 J7.9 J7.14 J7.20 J7.25 J7.30 J7.34 J7.39 J8.2 J9.1 J10.1 J14.1 J15.1 LED1.K pad.1@4.445,91.059 pad.1@16.129,91.04 pad.1@27.686,91.04 pad.1@50.927,91.059 pad.1@62.611,91.059 pad.1@74.295,91.04 pad.1@85.852,91.059 pad.3@62,47.175 pad.4 pad.7 R2.1 R3.1 R5.1 RA1.1 U1.1 U1.6 U2.1 U2.6 U3.1 U3.6 U4.1 U4.6 U5.1 U5.6 U6.1 U6.6 U7.1 U7.6 U8.1 U8.6 U9.2 U10.2 U11.19 U11.20 U11.39 U12.3 U12.4 U13.4 U13.6 U14.2 U15.6 | length 162.3
  Top Layer w1.27: J1.1@37.611,56.737 35.757,56.737 35.198,56.178 35.198,52.662 37.992,49.868 37.992,48.54 J10.1 38.678,48.279 J5.1 ; U13.4@59.46,43.951 U13.4 ; U9.2 U9.2@62,27.526 ; LED1.K@95.954,28.46 LED1.K
  Bottom Layer w1.27: U1.6 U2.6 U3.6 U4.6 U5.6 U6.6 U7.6 U8.6 ; R5.1 43.529,27.84 43.949,27.42 J2.2 47.58,27.5 U9.2 ; U12.3 U12.4
  Bottom Layer w1.778: U15.6 56.691,18.849 58.237,18.849 61.046,16.04 J4.1 69.565,16.04 73.077,19.552 76.737,19.552 78.829,17.46 U10.2 83.289,17.46 87.169,13.58 J15.1
GPIO18: J7.12 J10.2 | length 11.6
  Top Layer w0.254: J7.12 29.661,42.62 30.849,43.809 32.683,43.809 33.877,42.615 v1(33.877,42.259)
  Bottom Layer w0.254: v1(33.877,42.259) 37.618,46 J10.2
GPIO22: J7.15 J10.3 | length 32.1
  Top Layer w0.254: v1(37.535,33.903) 37.535,31.083 39.186,29.432 40.249,29.432 41.523,30.706 41.523,39.313 39.068,41.767 39.068,42.402 38.25,43.22 J10.3
  Bottom Layer w0.254: J7.15 33.039,37.54 33.745,38.246 36.849,38.246 37.916,37.179 37.916,34.487 37.865,34.436 37.865,34.233 v1(37.535,33.903)
GPIO23: J7.16 J10.4 | length 14.2
  Top Layer w0.254: v1(36.646,36.722) 39.008,39.084 39.008,40.92 J10.4
  Bottom Layer w0.254: J7.16 29.661,37.54 30.885,36.316 36.646,36.316 v1(36.646,36.722)
LED_DRV: R1.2 U11.30 | length 98
  Bottom Layer w0.254: U11.30 23.185,32.38 24.606,33.801 35.598,33.801 36.513,32.887 38.59,32.887 38.686,32.983 38.686,38.268 38.678,38.276 38.678,38.5 39.338,39.16 42.894,39.16 45.976,36.079 48.492,36.079 48.881,36.468 48.881,37.992 48.424,38.449 46.628,38.449 46.119,38.958 46.119,40.633 46.628,41.142 49.168,41.142 49.778,41.751 49.778,45.104 54.096,49.422 93.578,49.422 R1.2
LED_HI: LED1.A R1.1 | length 5.8
  Top Layer w0.254: LED1.A R1.1
LEDSTRIP_BPILL: J5.2 U11.33 | length 20.9
  Bottom Layer w0.254: U11.33 26.767,40 28.035,41.269 33.064,41.269 33.191,41.142 35.096,41.142 35.833,41.878 40.647,41.878 41.104,42.335 J5.2
LEDSTRIP_RPI: J6.2 J7.19 | length 38.7
  Bottom Layer w0.254: J7.19 36.005,32.46 36.315,32.15 45.815,32.15 46.655,31.31 62.527,31.31 66.059,34.842 66.059,37.46 J6.2
PCB_PRESENT: J7.22 R3.2 | length 27.5
  Top Layer w0.254: v1(27.324,21.863) 27.705,21.863 27.578,21.99 27.578,29.61 27.888,29.92 J7.22 ; v1(37.992,15.64) 37.992,15.508 R3.2 R3.2@40.5,13.386
  Bottom Layer w0.254: v1(27.324,21.863) 28.027,21.863 28.771,21.119 32.513,21.119 v1(37.992,15.64)
RPI_3V3: J7.1 U15.1 | length 54.5
  Top Layer w0.254: J7.1 33.237,55.32 33.826,54.731 33.826,51.327 35.452,49.701 35.452,45.663 36.646,44.469 39.084,44.469 39.77,43.783 39.77,41.784 42.031,39.523 42.031,19.018 46.222,14.827 v1(46.476,14.827)
  Bottom Layer w0.254: v1(46.476,14.827) 47.949,16.3 51.42,16.3 U15.1
RPI_SCL: J2.3 J7.5 U9.3 U10.3 U14.3 U15.5 | length 93.6
  Top Layer w0.254: J7.5 33.928,50.24 34.512,49.656 34.512,45.637 36.429,43.721 36.429,40.075 35.63,39.276 35.63,35.96 35.884,35.706 37.662,35.706 39.77,33.598 v1(39.77,30.448) ; U15.5 58.642,16.5 58.642,26.682 U9.3
  Bottom Layer w0.254: v1(39.77,30.448) 40.385,29.833 45.968,29.833 46.095,29.96 J2.3 47.58,30.04 U9.3 ; U15.5 58.249,14.751 70.072,14.751 72.401,17.08 U14.3 77.413,17.08 79.573,14.92 U10.3
RPI_SDA: J2.4 J7.3 U9.4 U10.4 U14.4 U15.3 | length 111.4
  Top Layer w0.254: J2.4@47.493,32.507 53.156,38.17 53.156,50.082 v1(51.801,51.437) ; J2.4 52.699,27.301 52.699,16.758 ; U15.3 U15.3@53.96,16.478 ; 52.699,16.758 53.955,16.479 U15.3@53.96,16.478 ; 52.699,16.758 52.978,16.478 U15.3@53.96,16.478
  Bottom Layer w0.254: J7.3 33.091,51.689 39.48,51.689 41.472,53.681 48.427,53.681 50.671,51.437 v1(51.801,51.437) ; J2.4 47.58,32.58 U9.4 ; U15.3 53.96,15.107 56.754,12.313 68.904,12.313 71.131,14.54 U14.4 77.413,14.54 79.573,12.38 U10.4
RSSI_1: RA1.2 U1.4 U11.5 | length 100.1
  Top Layer w0.254: 4.21,48.89 5.48,47.62 ; U11.5 5.25,47.62 4.21,48.66 4.21,82.315 5.315,83.42 U1.4
  Bottom Layer w0.254: v1(4.21,66.059) 6.674,68.523 12.389,68.523 13.456,67.456 13.456,65.282 15.346,63.392 18.637,63.392 20.523,65.278 45.129,65.278 46.355,64.052 46.355,62.992 44.958,61.595 44.958,60.122 RA1.2
RSSI_2: RA1.3 U2.4 U11.6 | length 105
  Top Layer w0.254: U11.6 8.141,46.461 8.141,48.109 7.449,48.801 5.72,48.801 5.226,49.295 5.226,81.68 5.785,82.239 10.189,82.239 11.37,83.42 U2.4
  Bottom Layer w0.254: U11.6 9.646,47.966 9.646,51.175 11.932,53.461 20.89,53.461 21.391,53.961 32.689,53.961 34.199,52.451 38.621,52.451 41.619,55.449 42.399,56.229 43.847,56.229 45.036,55.04 RA1.3
RSSI_3: RA1.4 U3.4 U11.7 | length 114.4
  Top Layer w0.254: U11.7 8.649,44.429 8.649,49.616 8.401,49.864 8.401,65.424 7.004,66.821 v1(7.004,81.172) ; RA1.4 48.889,52.5 48.889,81.832 v1(48.406,82.315)
  Bottom Layer w0.254: v1(7.004,81.172) 8.071,82.239 21.832,82.239 23.013,83.42 U3.4 34.855,83.42 36.036,82.239 48.33,82.239 v1(48.406,82.315)
RSSI_4: RA1.5 U4.4 U11.8 | length 84.4
  Top Layer w0.254: U4.4 46.412,83.42 46.882,82.95 46.882,82.061 48.279,80.664 48.279,62.376 47.204,61.301 46.342,61.301 45.866,60.825 45.866,52.851 45.917,52.8 45.917,50.417 46.374,49.96 RA1.5
  Bottom Layer w0.254: U11.8 10.968,40 19.933,48.965 33.877,48.965 35.401,50.489 40.36,50.489 40.889,49.96 RA1.5
RSSI_5: RA1.6 U5.4 U11.9 | length 89.5
  Top Layer w0.254: RA1.6 48.889,47.42 50.151,48.682 50.151,81.596 51.975,83.42 U5.4
  Bottom Layer w0.254: U11.9 10.358,37.46 19.247,46.349 32.937,46.349 36.31,49.721 39.687,49.721 41.942,47.466 42.636,47.466 42.682,47.42 RA1.6
RSSI_6: RA1.7 U6.4 U11.10 | length 107
  Top Layer w0.254: v1(58.185,50.743) 58.185,73.552 57.296,74.441 55.264,74.441 54.68,75.025 54.68,81.553 55.264,82.137 61.258,82.137 62.541,83.42 U6.4
  Bottom Layer w0.254: U11.10 13.633,34.92 19.906,41.192 25.952,41.192 28.594,43.834 34.004,43.834 37.128,46.958 42.425,46.958 42.472,46.912 45.256,46.912 47.288,44.88 RA1.7 48.66,44.88 54.523,50.743 v1(58.185,50.743)
RSSI_7: RA1.8 U7.4 U11.11 | length 177.4
  Top Layer w0.254: v1(3.429,83.312) 3.429,69.376 3.702,69.103 3.702,67.456 3.194,66.948 3.194,34.917 5.731,32.38 U11.11 ; RA1.8 46.095,42.619 46.095,48.228 46.628,48.762 49.498,48.787 v1(49.498,83.839)
  Bottom Layer w0.254: v1(3.429,83.312) 3.429,84.328 3.702,84.601 49.422,84.601 49.549,84.474 ; v1(49.498,83.839) 49.498,84.423 49.549,84.474 ; U7.4 69.584,83.42 68.403,84.601 55.382,84.601 55.255,84.474 49.549,84.474
RSSI_8: RA1.9 U8.4 U11.12 | length 236.7
  Top Layer w0.254: v1(2.178,79.699) 2.921,78.956 2.921,69.166 3.194,68.893 3.194,68.051 2.686,67.543 2.686,32.532 5.378,29.84 U11.12 ; v1(87.293,45.383) 87.293,81.286 89.427,83.42 U8.4
  Bottom Layer w0.254: v1(2.178,79.699) 91.84,79.699 92.399,80.258 92.399,83.115 92.094,83.42 U8.4 ; RA1.9 52.906,39.8 55.721,42.615 55.721,48.355 56.28,48.914 83.763,48.914 v1(87.293,45.383)
RTC_BAT: J1.2 U11.1 | length 33.3
  Bottom Layer w0.254: U11.1 7.031,57.702 17.113,57.702 18.383,58.972 31.198,58.972 35.897,54.273 J1.2
RX_CLK_ALL: U1.7 U2.7 U3.7 U4.7 U5.7 U6.7 U7.7 U8.7 U11.32 | length 124.8
  Top Layer w0.254: U2.7 22.244,75.8 23.032,75.012 23.032,66.651 19.044,62.663 19.044,39.383 20.967,37.46 U11.32
  Bottom Layer w0.254: U1.7 15.31,75.8 15.323,75.787 16.935,75.787 16.948,75.8 U2.7 U3.7 U4.7 U5.7 U6.7 U7.7 U8.7
RX_DATA_ALL: U1.9 U2.9 U3.9 U4.9 U5.9 U6.9 U7.9 U8.9 U11.31 | length 121
  Top Layer w0.254: U2.9 21.143,66.42 18.028,63.305 18.028,37.535 20.642,34.92 U11.31
  Bottom Layer w0.254: U1.9 U2.9 U3.9 U4.9 U5.9 U6.9 U7.9 U8.9
RX_SEL_1: U1.8 U11.34 | length 44.2
  Top Layer w0.254: U1.8 11.424,73.26 15.132,69.552 15.132,40.684 v1(14.929,40.481)
  Bottom Layer w0.254: v1(14.929,40.481) 15.081,40.481 17.14,42.54 U11.34
RX_SEL_2: U2.8 U11.35 | length 52
  Top Layer w0.254: U2.8 21.355,73.26 22.524,72.091 22.524,67.083 18.536,63.095 18.536,38.957 21.228,36.265 22.752,36.265 23.387,36.9 23.387,43.838 22.696,44.529 22.696,45.08 U11.35
RX_SEL_3: U3.8 U11.36 | length 37.9
  Top Layer w0.254: U11.36 20.897,47.62 19.577,48.94 19.577,62.478 23.565,66.465 23.565,71.444 25.381,73.26 U3.8 32.786,74.06
RX_SEL_4: U4.8 U11.37 | length 63.2
  Top Layer w0.254: v1(13.786,51.124) 13.786,61.97 13.887,62.071 v1(13.887,62.198) ; U4.8 43.758,73.26 43.048,72.55 43.048,69.539 44.748,67.838 v1(44.748,63.519)
  Bottom Layer w0.254: v1(13.786,51.124) 21.036,51.124 U11.37 ; v1(13.887,62.198) 20.085,62.198 20.618,61.665 23.641,61.665 25.746,63.77 44.497,63.77 v1(44.748,63.519)
RX_SEL_5: U5.8 U11.21 | length 98.6
  Top Layer w0.254: v1(47.314,18.815) 46.628,18.815 46.095,19.348 46.095,33.598 46.206,33.709 46.206,35.182 46.095,35.293 46.095,40.456 46.628,40.989 48.33,40.989 50.659,43.318 50.659,70.941 52.978,73.26 U5.8
  Bottom Layer w0.254: U11.21 23.387,9.798 23.387,14.624 24.632,15.869 33.725,15.869 38.043,11.551 41.218,11.551 42.259,12.592 42.259,13.456 47.314,18.51 v1(47.314,18.815)
RX_SEL_6: U6.8 U11.22 | length 116.6
  Top Layer w0.254: v1(16.554,65.424) 15.996,64.865 15.996,16.048 19.983,12.06 U11.22 ; U6.8 68.726,73.26 69.107,72.879 v1(69.107,69.158)
  Bottom Layer w0.254: v1(16.554,65.424) 20.288,69.158 v1(69.107,69.158)
RX_SEL_7: U7.8 U11.23 | length 123.9
  Top Layer w0.254: v1(19.323,72.028) 18.586,71.291 18.586,64.582 17.52,63.516 17.52,21.025 20.136,18.409 22.752,18.409 23.387,17.774 23.387,14.878 23.109,14.6 U11.23
  Bottom Layer w0.254: v1(19.323,72.028) 69.158,72.028 70.39,73.26 U7.8
RX_SEL_8: U8.8 U11.24 | length 133.9
  Top Layer w0.254: v1(19.044,74.441) 18.078,73.476 18.078,64.793 17.012,63.726 17.012,20 19.872,17.14 U11.24
  Bottom Layer w0.254: v1(19.044,74.441) 83.585,74.441 84.766,73.26 U8.8
RXD: J4.5 J7.10 U11.26 | length 118.4
  Top Layer w0.254: U11.26 23.944,22.22 24.403,22.679 v1(24.403,45.104) ; J7.10@29.404,45.104 J7.10
  Bottom Layer w0.254: U11.26 13.533,22.22 9.722,18.409 5.988,18.409 6.071,18.326 6.071,18.321 5.379,17.629 5.379,16.651 6.071,15.959 8.438,15.959 10.814,13.583 16.067,13.583 21.311,8.339 22.716,8.339 23.917,9.541 23.917,9.567 25.164,10.814 33.547,10.814 34.817,9.544 63.519,9.544 67.183,5.88 J4.5 ; v1@24.459,45.16 J7.10
TXD: J4.4 J7.8 U11.27 | length 94.6
  Top Layer w0.254: v1(24.276,47.771) 24.037,47.771 23.381,47.115 23.381,44.591 23.367,44.576 23.895,44.048 23.895,36.689 23.717,36.512 23.717,25.546 22.931,24.76 U11.27 20.618,24.404 20.618,21.558 21.228,20.949 23.184,20.949 24.428,19.704 24.428,9.62 25.724,8.325 33.268,8.325 v1(35.503,10.56)
  Bottom Layer w0.254: v1(24.276,47.771) 29.389,47.771 J7.8 ; v1(35.503,10.56) 65.36,10.56 J4.4
VID1: pad.2@4.445,88.519 U1.2 | length 5.1
  Bottom Layer w0.254: pad.2@4.445,88.519 4.464,88.5 U1.2
VID2: pad.2@16.129,88.5 U2.2 | length 5
  Bottom Layer w0.254: pad.2@16.129,88.5 U2.2
VID3: pad.2@27.686,88.5 U3.2 | length 5.1
  Bottom Layer w0.254: pad.2@27.686,88.5 U3.2
VID4: pad.2@39.37,88.519 U4.2 | length 5.1
  Bottom Layer w0.254: pad.2@39.37,88.519 39.389,88.5 U4.2
VID5: pad.2@50.927,88.519 U5.2 | length 5.2
  Bottom Layer w0.254: pad.2@50.927,88.519 50.946,88.5 U5.2
VID6: pad.2@62.611,88.519 U6.2 | length 5.1
  Bottom Layer w0.254: pad.2@62.611,88.519 62.63,88.5 U6.2
VID7: pad.2@74.295,88.5 U7.2 | length 5.1
  Bottom Layer w0.254: pad.2@74.295,88.5 U7.2
VID8: pad.2@85.852,88.519 U8.2 | length 5.1
  Bottom Layer w0.254: pad.2@85.871,88.5 U8.2
VPWR_IN+: J15.2 R4.2 U10.6 | length 52.2
  Top Layer w1.27: v1(63.9,35.706) 68.853,35.706 77.489,27.07 77.489,11.811 U10.6
  Bottom Layer w1.016: R4.2 63.294,35.706 v1(63.9,35.706)
  Bottom Layer w1.27: U10.6 83.2,8.5 J15.2
VPWR_IN-: pad.2@59.46,47.175 U10.5 U12.2 U13.3 | length 59.1
  Top Layer w1.27: U12.2 78.5,28.98 79.013,28.467 79.013,12.763 ; 79.076,12.763 U10.5
  Bottom Layer w1.27: pad.2@59.46,47.126 57.62,45.286 57.571,45.286 56.92,44.635 U13.3 56.92,42.954 58.199,41.675 64.618,41.675 64.632,41.689 67.368,41.689 67.382,41.675 67.634,41.675 69.031,43.072 72.434,43.072 78.5,37.006 U12.2
VPWR_MON: R4.1 R5.2 U11.14 | length 100.6
  Bottom Layer w0.254: U11.14 11.575,24.76 12.843,26.029 35.884,26.029 38.856,29 46.374,29 46.604,28.77 63.416,28.77 64.51,29.864 64.51,32.531 67.405,35.427 67.405,37.992 66.745,38.652 64.84,38.652 63.773,39.719 56.128,39.719 55.162,38.754 51.594,38.754 R4.1 49.389,36.549 49.389,35.96 49,35.571 42.429,35.571 R5.2
pads on no net: J7.7 J7.17 J7.21 J7.23 J7.24 J7.26 J7.27 J7.28 J7.29 J7.31 J7.32 J7.33 J7.35 J7.36 J7.37 J7.38 J7.40 U11.2 U11.3 U11.4 U11.28 U11.29 U12.1 U12.6 U13.1 U13.2 U14.5 U14.6 U14.7 U14.8

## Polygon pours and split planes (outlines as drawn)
GND on Top Layer "GND_TOP" (solid, pour order 0): 0.4,98.584 0.4,97.682 0.4,83.839 7.639,83.839 7.639,79.775 7.639,63.119 20.053,63.119 20.053,50.419 24.911,50.419 24.911,31.49 31.007,31.49 30.886,41.548 28.213,41.548 28.213,48.787 33.195,48.787 33.195,51.632 28.111,51.632 28.111,57.017 30.423,59.023 32.506,59.023 34.487,60.801 40.786,60.801 40.786,65.17 45.993,65.17 45.993,79.775 42.818,79.775 42.818,84.728 63.582,84.982 63.582,83.839 63.582,81.87 63.582,68.472 50.997,68.472 50.997,56.534 51.092,52.61 53.999,51.592 53.999,17.672 57.042,17.672 58.248,17.672 58.248,18.878 58.248,29.737 58.248,29.991 63.074,29.991 63.074,28.848 61.36,28.848 60.217,27.705 60.217,26.054 62.249,26.054 63.392,26.054 64.408,26.054 64.941,26.587 64.941,32.912 69.234,32.912 79.521,32.912 79.521,23.514 86.252,23.514 88.571,23.514 92.602,23.514 92.602,17.799 88.03,17.799 85.172,14.941 85.172,12.465 85.173,6.75 83.744,5.321 73.647,5.321 73.647,18.173 76.473,18.208 76.473,21.101 67.879,21.101 65.297,19.164 65.297,14.37 69.234,14.37 69.234,9.798 65.575,9.798 65.551,11.576 64.408,13.024 46.125,13.024 41.548,18.233 41.548,29.229 38.76,29.229 35.198,32.791 35.198,39.77 35.96,40.423 35.96,43.216 34.914,44.404 34.08,45.351 34.08,46.679 31.312,46.679 30.753,46.679 30.753,44.215 33.195,44.215 34.817,42.593 34.817,41.76 33.547,40.913 33.547,27.975 32.579,26.308 30.626,26.308 30.626,21.101 28.213,21.101 27.959,21.101 26.435,21.101 26.435,17.164 24.911,17.164 24.911,11.068 20.053,11.068 14.802,16.319 14.802,21.895 12.973,21.895 12.973,48.549 12.319,49.287 12.319,62.23 8.718,62.23 8.718,43.453 8.718,21.895 2.722,21.895 2.722,83.439 0.4,83.439 0.4,0.4 69.234,0.4 85.363,0.4 99.46,0.4 99.46,10.56 99.46,99.46 83.204,99.46 0.4,99.46 0.4,99.079
GND on Top Layer "GND_TOP2" (solid, pour order 6): 0.4,84.601 3.702,84.601 3.702,80.137 3.692,80.147 0.4,80.147
GND on Top Layer "GND_TOP3" (solid, pour order 8): 8.789,63.246 12.316,63.246 12.316,61.598 12.319,61.595 8.763,61.595 8.763,63.22 8.789,63.246
GND on Top Layer "GND_TOP4" (solid, pour order 10): 24.892,46.707 35.052,46.784 35.052,21.844 34.036,20.828 24.892,20.828
GND on Bottom Layer "GND_BOT" (solid, pour order 2): 0.4,99.46 0.4,70.123 8.782,70.123 8.782,85.236 70.504,85.236 70.504,81.934 89.3,81.934 89.3,84.728 91.734,84.728 91.734,76.981 92.475,76.981 92.475,68.961 19.685,68.961 19.685,59.309 31.242,59.309 36.195,54.356 48.387,54.356 50.546,52.197 59.055,52.197 59.055,49.789 92.856,50.038 92.856,26.67 86.506,26.67 86.506,6.115 73.679,6.115 73.679,13.735 71.393,13.735 68.853,11.195 68.853,8.401 20.339,8.401 15.64,12.973 10.56,12.973 9.713,13.481 4.591,13.481 4.591,27.451 3.429,28.613 3.429,67.329 0.4,67.329 0.4,0.4 81.68,0.4 99.46,0.4 99.46,84.982 99.46,99.46 1.035,99.46
GND on Bottom Layer "GND_BOT2" (solid, pour order 4): 5.588,74.549 0.381,74.549 0.381,57.531 5.588,57.531

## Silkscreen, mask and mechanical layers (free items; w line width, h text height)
Top Overlay:
  rectangle: 5.861,64.765 8.03,65.157
  lines w0.203: 50.57,61.145 50.57,63.685 68.35,63.685 68.35,61.145 ; 57.682,45.143 58.571,46.032 ; 60.476,45.27 60.984,45.778 64.921,45.778 ; 63.27,43.873 64.032,43.873 66.191,46.032
  text "V1" at 1.5,88.25 h0.9
  text "V2" at 13,88.25 h0.9
  text "V3" at 24.75,88.25 h0.9
  text "V4" at 36.25,88.25 h0.9
  text "V5" at 48,88.25 h0.9
  text "V6" at 59.5,88.25 h0.9
  text "V7" at 71.25,88.25 h0.9
  text "V8" at 82.75,88.25 h0.9
  text "A1" at 1.5,85.75 h0.9
  text "A2" at 13,85.75 h0.9
  text "A3" at 24.75,85.75 h0.9
  text "A4" at 36.25,85.75 h0.9
  text "A5" at 48,85.75 h0.9
  text "A6" at 59.5,85.75 h0.9
  text "A7" at 71.25,85.75 h0.9
  text "A8" at 82.75,85.75 h0.9
  text "Boot0" at 15.64,62.63 h0.91
  text "Boot1" at 9.036,62.503 h0.91
  text "5V_Pill" at 74.192,61.526 h0.91
  text "J7" at 31.515,61.233 h1.52
  text "BPill_I2C" at 40.278,58.947 h0.91 r270
  text "+3V3 Regulator" at 53.613,58.058 h0.91
  text "GND" at 53.364,55.811 h0.91 r270
  text "BAT" at 34.69,55.518 h0.91 r270
  text "+3.3V" at 74.446,54.16 h0.91
  text "Vout" at 66.699,51.747 h0.91 r270
  text "Vin" at 59.333,51.112 h0.91 r270
  text "GND" at 61.492,51.112 h0.91 r270
  text "GND" at 64.032,51.112 h0.91 r270
  text "+5V Regulator" at 73.679,47.771 h0.91
  text "RPi_GPIO" at 35.071,46.374 h0.91 r270
  text "FAN" at 92.075,45.974 h0.91
  text "1" at 93.091,44.577 h0.91
  text "LED_BPill" at 43.58,44.342 h0.91 r270
  text "100" at 95.523,43.072 h0.91 r270
  text "Pi_LED" at 68.091,39.008 h0.91 r270
  text "10K 1%" at 53.359,37.484 h0.91
  text "GND" at 91.713,36.214 h0.91
  text "Vout" at 85.617,36.061 h0.91 r270
  text "1K 1%" at 39.516,35.579 h0.91 r270
  text "GND" at 80.622,35.452 h0.91 r270
  text "GND" at 83.119,35.452 h0.91 r270
  text "Vin" at 78.124,35.3 h0.91 r270
  text "+" at 98.044,32.004 h1.2
  text "Temp_Baro" at 51.835,30.88 h0.91
  text "RPi_I2C" at 44.596,29.483 h0.91 r270
  text "+5V" at 86.633,28.34 h0.91
  text "DTR_RES" at 91.44,23.749 h0.91 r270
  text "FAN" at 96.393,22.733 h0.91
  text "100K" at 39.516,22.117 h0.91 r270
  text "2" at 97.282,21.209 h0.91
  text "RTC Breakout" at 71.774,18.688 h0.91 r270
  text "Pi_RTC" at 54.864,13.589 h0.91
  text "BPill_FTDI" at 64.662,12.973 h0.91 r270
  text "1K" at 40.151,8.782 h0.91 r270
  text "RotorHazard_S32_BPill" at 7.239,4.445 h1.2
  text "B" at 48.514,4.318 h10
  text "J15" at 88.792,3.194 h1.52
  text "http://www.rotorhazard.com" at 7.366,2.286 h1.2
Bottom Overlay:
  lines w0.203: 35.048,34.036 34.544,34.036 34.544,28.448 35.052,28.448
  text "RotorHazard_S32_BPill  Rev 1.0  bduris  12/2020" at 90.17,94.869 h1.8
  text "C" at 64.897,4.318 h25
Board Outline:
  the board outline again, w0.203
